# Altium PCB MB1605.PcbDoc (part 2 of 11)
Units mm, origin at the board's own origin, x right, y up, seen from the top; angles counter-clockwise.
Board outline 100 x 79.6 mm, 6 copper layers (Top Layer, Signal Layer 1, Signal Layer 2, Signal Layer 3, Signal Layer 4, Bottom Layer), stack 1.549 mm thick; 644 components, 529 nets, 2853 pads, 1462 vias.
Unrouted connection lines stored in the file: 2.
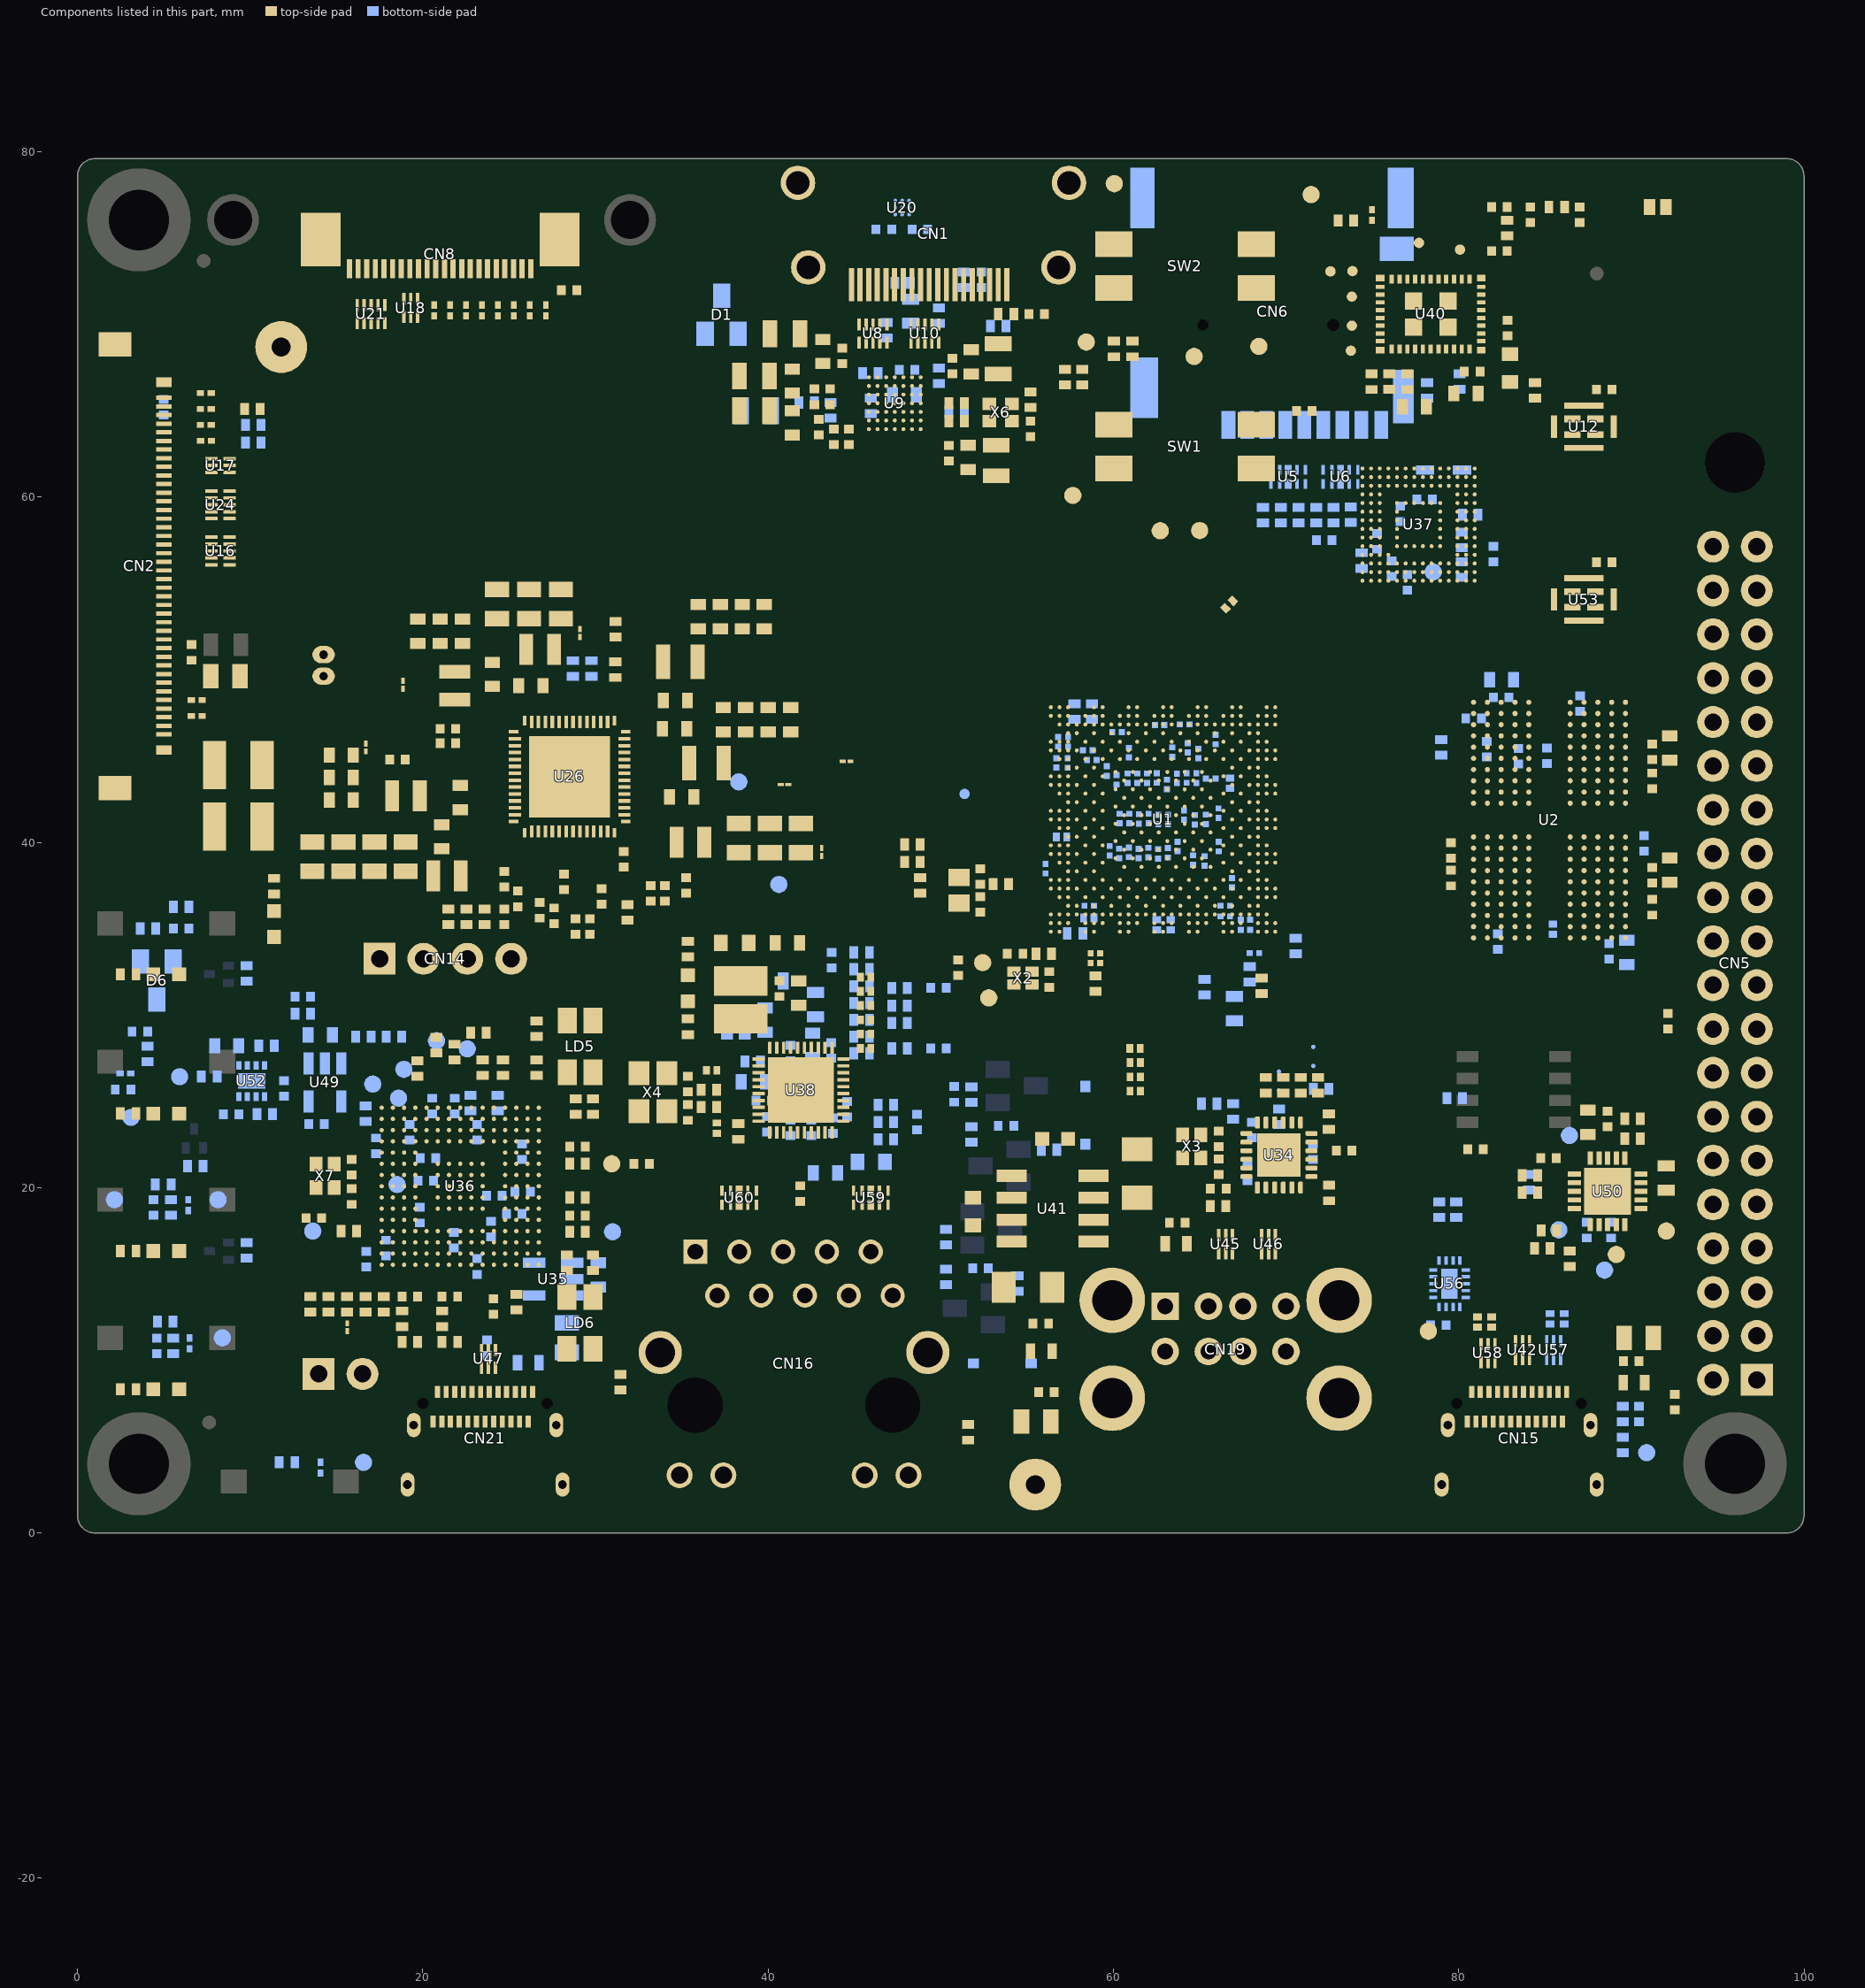
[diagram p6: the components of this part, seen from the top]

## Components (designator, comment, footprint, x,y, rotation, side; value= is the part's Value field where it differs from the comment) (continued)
R114 "" R0402 47.62,28.065 r0 bottom value=4K7
R120 "Resistor" R0201_H0P23 45.645,30.544 r180 top value=22R
R121 "Resistor" R0201_H0P23 45.645,29.72 r180 top value=22R
R122 "Resistor" R0402 58.2,66.95 r90 top value=1K
R123 "Resistor" R0402 61.1,68.575 r270 top value=1K
R124 "Resistor" R0402 60.025,68.575 r270 top value=1K
R125 "Resistor" R0402 26.59,29.207 r90 top value=10K
R126 "Resistor" R0402 4.963,20.187 r0 bottom value=330R
R127 "Resistor" R0402 5.082,12.237 r0 bottom value=330R
R128 "Resistor" R0402 5.413,18.85 r90 bottom value=100K
R129 "Resistor" R0402 20.79,28.257 r90 top value=0R
R130 "Resistor" R0402 28.85,24.7 r90 top value=330R
R131 "Resistor" R0402 29.858,24.7 r270 top value=1K
R132 "Resistor" R0402 29.85,15.644 r90 top value=330R
R133 "Resistor" R0402 28.35,15.644 r90 top value=1K
R134 "Resistor" R0402 21.84,27.857 r90 top value=33R
R135 "Resistor" R0402 5.532,10.837 r90 bottom value=100K
R136 "Resistor" R0402 2.936,8.327 r0 top value=360R
R137 "Resistor" R0402 6.813,21.252 r0 bottom value=100K
R138 "Resistor" R0402 2.936,24.294 r180 top value=270R
R139 "Resistor" R0402 4.056,27.75 r90 bottom value=1K
R140 "Resistor" R0402 7.627,26.441 r0 bottom value=100R
R141 "Resistor" R0402 9.786,16.377 r90 bottom value=100K
R142 "Resistor" R0402 2.936,16.327 r180 top value=300R
R143 "Resistor" R0402 9.786,32.411 r90 bottom value=100K
R144 "" R0402 2.936,32.361 r0 top value=120R
R147 "Resistor" R0201_H0P23 45.645,28.898 r180 top value=22R
R148 "Resistor" R0201_H0P23 45.644,28.065 r180 top value=22R
R149 "Resistor" R0201_H0P23 45.645,32.185 r180 top value=22R
R150 "Resistor" R0201_H0P23 45.645,31.365 r180 top value=22R
R151 "Resistor" R0402 35.35,33.82 r90 top value=270R
R153 "Resistor" R0402 23.465,26.957 r90 top value=33R
R154 "Resistor" R0402 24.64,26.957 r90 top value=0R
R155 "Resistor" R0402 26.59,26.957 r270 top value=0R
R156 "Resistor" R0402 19.69,26.907 r90 top value=10K
R158 "" R0402 35.35,29.32 r90 top value=4K7
R161 "Resistor" R0201_H0P23 62.506,35.225 r270 bottom value=22R
R162 "Resistor" R0402 51.775,23.075 r90 bottom value=100K
R164 "Resistor" R0201_H0P23 63.319,35.225 r270 bottom value=22R
R167 "Resistor" R0201_H0P23 61.245,28.065 r180 top value=22R
R173 "Resistor" R0201_H0P23 61.26,27.24 r180 top value=22R
R176 "Resistor" R0201_H0P23 36.725,26.8 r0 top value=22R
R178 "Resistor" R0201_H0P23 61.26,26.415 r180 top value=22R
R181 "Resistor" R0402 28.965,21.382 r0 top value=100R
R182 "" R0402 36.575,25.675 r0 top value=0R
R185 "Resistor" R0201_H0P23 61.26,25.59 r180 top value=22R
R187 "Resistor" R0402 50.297,14.825 r90 bottom value=100K
R188 "" R0402 36.575,24.675 r0 top value=0R
R191 "" R0402 46.82,24.8 r0 bottom value=1K5
R194 "Resistor" R0402 28.965,19.432 r0 top value=3K
R195 "" R0402 46.82,23.8 r0 bottom value=1K5
R196 "Resistor" R0201_H0P23 37.025,23.45 r90 top value=22R
R199 "" R0402 38.275,23.25 r270 top value=2K49
R200 "Resistor" R0402 54.438,14.437 r270 bottom value=100K
R205 "Resistor" R0402 46.82,22.8 r0 bottom value=10K
R207 "Resistor" R0402 15.715,17.482 r180 top value=33R
R209 "Resistor" R0402 28.965,17.443 r0 top value=33R
R210 "Resistor" R0402 11.386,37.465 r270 top value=270R
R211 "Resistor" R0402 25.415,13.362 r90 top value=0R
R212 "Resistor" R0402 13.49,13.232 r270 top value=0R
R213 "Resistor" R0402 14.54,13.232 r270 top value=10K
R214 "Resistor" R0402 15.615,13.232 r270 top value=10K
R215 "Resistor" R0402 16.69,13.232 r270 top value=10K
R216 "Resistor" R0402 17.74,13.232 r270 top value=5K1
R217 "Resistor" R0402 18.795,12.407 r270 top value=100K
R218 "Resistor" R0402 21.115,12.407 r270 top value=100K
R219 "Resistor" R0402 89.5,6.879 r90 bottom value=140K
R220 "Resistor" R0402 89.5,5.1 r90 bottom value=10K
R221 "Resistor" R0402 19.245,11.057 r0 top value=5K1
R222 "Resistor" R0402 21.565,11.057 r0 top value=5K1
R223 "Resistor" R0402 85.218,17.522 r180 top value=10K
R224 "Resistor" R0402 84.13,19.71 r180 top value=1K5
R225 "Resistor" R0603 92.025,20.56 r90 top value=22mR
R226 "Resistor" R0402 16.565,28.75 r0 bottom value=3K9
R227 "Resistor" R0402 18.315,28.75 r180 bottom value=100K
R228 "Resistor" R0402 84.13,20.71 r180 top value=1K5
R229 "Resistor" R0402 16.69,24.294 r90 bottom value=100K
R230 "Resistor" R0402 13.042,30.075 r0 bottom value=3K
R231 "Resistor" R0402 90.075,22.835 r0 top value=24K
R232 "Resistor" R0402 90.075,23.99 r180 top value=100K
R233 "" R0402 31.44,8.736 r90 top value=510R
R234 "" R0402 51.575,5.825 r270 top value=510R
R239 "Resistor" R0402 10.836,24.257 r180 bottom value=100K
R240 "Resistor" R0402 24.335,24.9 r270 bottom value=1K3
R241 "Resistor" R0402 22.765,24.9 r270 bottom value=1K8
R242 "Resistor" R0402 10.936,28.217 r0 bottom value=3K9
R245 "Resistor" R0402 48.355,39.873 r180 top value=1K5
R246 "Resistor" R0402 84.074,20.308 r270 bottom value=1K5
R248 "Resistor" R0402 80.657,58.98 r0 bottom value=10K
R250 "Resistor" R0402 57.744,47.57 r90 bottom value=200R
R251 "Resistor" R0402 58.751,47.57 r90 bottom value=200R
R260 "Resistor" R0402 28.689,50.071 r270 bottom value=1K5
R261 "Resistor" R0402 29.763,50.071 r270 bottom value=1K5
R267 "" R0402 57.773,34.723 r180 bottom value=0R
R269 "" R0402 58.956,31.808 r90 top value=0R
R272 "Resistor" R0402 48.805,37.505 r270 top value=10K
R286 "" R0402 67.89,32.365 r90 bottom value=0R
R292 "" R0402 45.42,29.72 r0 bottom value=4K7
R293 "" R0402 45.42,30.688 r0 bottom value=4K7
R303 "" R0402 45.42,27.785 r0 bottom value=4K7
R304 "" R0402 45.42,31.67 r0 bottom value=4K7
R305 "" R0402 45.42,32.651 r0 bottom value=4K7
R310 "" R0603 40.175,31.975 r0 bottom value=0R
R313 "" R0603 42.75,30.6 r90 bottom value=0R
R318 "" R0402 38.65,29.275 r90 bottom value=1K5
R319 "" R0402 37.625,29.275 r270 bottom value=4K7
R322 "" R0402 39.1,27.3 r180 bottom value=4K7
R323 "Resistor" R0402 72.483,19.687 r90 top value=10K
R324 "Resistor" R0402 72.477,23.817 r270 top value=10K
R325 "Resistor" R0402 79.775,25.178 r0 bottom value=1M
R327 "Resistor" R0402 86.438,15.875 r90 top value=100K
SB1 "SB_ON" SOLDER-BRIDGE_R0603-0R 69.587,26.223 r270 bottom
SB2 "SB_ON" SOLDER-BRIDGE_R0603-0R 71.577,27.65 r270 bottom
SW1 "SWITCH_2WAY" SWI_C&K_SDA02H1SBD_2POS 64.15,62.925 r90 top
SW2 "SWITCH_2WAY" SWI_C&K_SDA02H1SBD_2POS 64.15,73.375 r90 top
TP1 "Test Point" TP_SMD_0-6MM 80.075,74.331 r90 top
TP2 "Test Point" TP_SMD_1MM 2.136,19.3 r180 bottom
TP3 "Test Point" TP_SMD_1MM 8.136,19.3 r180 bottom
TP4 "Test Point" TP_SMD_1MM 40.618,37.56 r180 bottom
TP5 "Test Point" TP_SMD_1MM 8.386,11.3 r90 bottom
TP6 "Test Point" TP_SMD_1MM 3.095,24.07 r90 bottom
TP7 "Test Point" TP_SMD_1MM 5.913,26.425 r90 bottom
TP8 "Test_pin_conn_black" TP_PTH-1P02MM_TEST-TERMINAL_RS_101-2391_BLACK 11.799,68.689 r270 top value=TP
TP9 "Test Point" TP_SMD_0-6MM 77.7,74.725 r90 top
TP10 "Test Point" TP_SMD_0-6MM 73.754,68.475 r90 top
TP11 "Test Point" TP_SMD_1MM 86.412,23.025 r90 bottom
TP12 "Test Point" TP_SMD_1MM 52.427,33.031 r90 top
TP13 "Test Point" TP_SMD_1MM 20.79,28.507 r90 bottom
TP14 "Test Point" TP_SMD_0-6MM 73.81,69.925 r90 top
TP15 "Test Point" TP_SMD_1MM 64.995,58.058 r270 top
TP16 "Test Point" TP_SMD_1MM 62.711,58.047 r270 top
TP17 "Test Point" TP_SMD_0-6MM 72.573,73.072 r180 top
TP18 "Test Point" TP_SMD_0-6MM 51.376,42.803 r90 bottom
TP19 "Test Point" TP_SMD_0-6MM 73.844,73.087 r90 top
TP20 "Test Point" TP_SMD_0-6MM 73.81,71.607 r90 top
TP21 "Test Point" TP_SMD_1MM 78.516,55.665 r90 bottom
TP22 "Test Point" TP_SMD_1MM 16.565,4.09 r90 bottom
TP23 "Test Point" TP_SMD_1MM 57.651,60.096 r270 top
TP24 "Test Point" TP_SMD_1MM 64.675,68.143 r270 top
TP25 "Test Point" TP_SMD_1MM 68.425,68.725 r270 top
TP26 "Test Point" TP_SMD_1MM 18.9,26.85 r180 bottom
TP27 "Test Point" TP_SMD_1MM 18.505,20.182 r180 bottom
TP28 "Test Point" TP_SMD_1MM 17.098,26 r90 bottom
TP29 "Test Point" TP_SMD_1MM 18.59,25.182 r90 bottom
TP30 "Test Point" TP_SMD_1MM 38.304,43.502 r90 bottom
TP31 "Test Point" TP_SMD_1MM 58.425,68.975 r270 top
TP32 "Test Point" TP_SMD_1MM 71.45,77.525 r270 top
TP33 "Test Point" TP_SMD_1MM 30.94,21.382 r90 top
TP34 "Test Point" TP_SMD_1MM 78.243,11.686 r270 top
TP35 "Test Point" TP_SMD_1MM 90.888,4.65 r90 bottom
TP36 "Test Point" TP_SMD_1MM 85.798,17.551 r270 bottom
TP37 "Test Point" TP_SMD_1MM 88.449,15.218 r270 bottom
TP38 "Test Point" TP_SMD_1MM 89.125,16.131 r270 top
TP39 "Test Point" TP_SMD_1MM 92.025,17.49 r270 top
TP40 "Test Point" TP_SMD_1MM 30.985,17.443 r90 bottom
TP41 "Test Point" TP_SMD_1MM 13.625,17.482 r90 bottom
TP42 "Test Point" TP_SMD_1MM 52.78,30.993 r90 top
TP43 "Test Point" TP_SMD_1MM 22.575,28.041 r90 bottom
TP44 "Test Point" TP_SMD_1MM 60.05,78.15 r270 top
TP2000 "Test_pin_conn_black" TP_PTH-1P02MM_TEST-TERMINAL_RS_101-2391_BLACK 55.47,2.8 r90 top value=TP
U1 "STM32MP257FAK3" ICC_TFBGA424_14X14_P050_H1P20_CODE-B0A2 62.875,41.325 r0 top locked
U2 "MT53E1G32D2FW-046 WT:C" ICC_TFBGA200_10X14P5_P080_H1P05_PS0P3 85.26,41.29 r180 top locked
U3 "ESD-TRANSIL" ESD_ST0201 7.442,63.25 r0 top value=ESDZL5-1F4
U4 "ESD-TRANSIL" ESD_ST0201 7.429,66.025 r0 top value=ESDZL5-1F4
U5 "HSP051-4M10" ESD_UQFN-10L_2P5X1_P050 70.125,61.172 r0 bottom
U6 "HSP051-4M10" ESD_UQFN-10L_2P5X1_P050 73.154,61.172 r0 bottom
U7 "ESD-TRANSIL" ESD_ST0201 7.429,65.1 r0 top value=ESDZL5-1F4
U8 "ECMF4-40A100N10" ESD_UQFN-10L_2P25X1P4_P040 46.072,69.473 r180 top
U9 "ADV7535BCBZ" ICC_WLCSP49_3P46X3P46_P050 47.336,65.435 r0 top
U10 "ECMF4-40A100N10" ESD_UQFN-10L_2P25X1P4_P040 49.079,69.473 r180 top
U11 "ESD-TRANSIL" ESD_ST0201 20.65,70.813 r270 top value=ESDZL5-1F4
U12 "IMP34DT05TR" MIC_HCLGA_3X4X1_4LD 86.75,64.07 r90 top
U13 "ESD-TRANSIL" ESD_ST0201 7.429,64.175 r0 top value=ESDZL5-1F4
U14 "ESD-TRANSIL" ESD_ST0201 23.425,70.813 r270 top value=ESDZL5-1F4
U15 "ESD-TRANSIL" ESD_ST0201 14.062,3.778 r270 bottom value=ESDZL5-1F4
U16 "ECMF4-40A100N10" ESD_UQFN-10L_2P25X1P4_P040 8.277,56.875 r270 top
U17 "ECMF2-40A100N6" ESD_UQFN-6L_1P45X1P4_P040 8.277,61.825 r270 top
U18 "ECMF2-40A100N6" ESD_UQFN-6L_1P45X1P4_P040 19.3,70.95 r180 top
U19 "ESD-TRANSIL" ESD_ST0201 26.2,70.813 r270 top value=ESDZL5-1F4
U20 "HDMI05-CL02F3" ESD_FLIP-CHIP_BGA9_1P14X1P14_P040 47.764,76.769 r90 bottom
U21 "ECMF4-40A100N10" ESD_UQFN-10L_2P25X1P4_P040 17,70.6 r180 top
U22 "ESD-TRANSIL" ESD_ST0201 6.909,48.25 r0 top value=ESDZL5-1F4
U23 "ESD-TRANSIL" ESD_ST0201 6.909,47.325 r0 top value=ESDZL5-1F4
U24 "ECMF4-40A100N10" ESD_UQFN-10L_2P25X1P4_P040 8.277,59.55 r270 top
U25 "ESD-TRANSIL" ESD_ST0201 6.413,18.987 r270 bottom value=ESDZL5-1F4
U26 "STPMIC25APQR" ICC_QFN56-EPAD_6P5X6P5_P040 28.5,43.8 r90 top
U27 "ESD-TRANSIL" ESD_ST0201 6.493,10.975 r270 bottom value=ESDZL5-1F4
U28 "ESD-TRANSIL" ESD_ST0201 2.77,26.627 r180 bottom value=ESDALC6V1-1U2
U29 "ESD-TRANSIL" ESD_ST0201 21.575,70.813 r270 top value=ESDZL5-1F4
U31 "ESD-TRANSIL" ESD_ST0201 22.5,70.813 r270 top value=ESDZL5-1F4
U32 "ESD-TRANSIL" ESD_ST0201 24.35,70.813 r270 top value=ESDZL5-1F4
U33 "ESD-TRANSIL" ESD_ST0201 25.275,70.813 r270 top value=ESDZL5-1F4
U34 "USB2422-I/MJ" ICC_SQFN24-EPAD_4X4_P050 69.587,21.888 r90 top
U35 "ST730M33R" ICC_SOT23-5L_H1P45 27.546,14.7 r270 bottom
U36 "STLINK-V3EC" ICC_UFBGA201_176+25_10X10_P065 22.165,20.082 r0 top value=STM32F723IEK6
U37 "eMMC_THGBMUG6C1LBAIL" ICC_WFBGA153_13X11P5_P050 77.675,58.405 r0 top value=THGBMUG6C1LBAIL
U38 "RTL8211F-CG" ICC_QFN40-EPAD_5X5_P040 41.9,25.65 r90 top
U39 "ESD-TRANSIL" ESD_ST0201 27.125,70.813 r270 top value=ESDZL5-1F4
U40 "LBEE5KL1YN-814" MOD_WLAN-BT_MURATA_LBEE5KL1YN-814 78.375,70.6 r180 top
U41 "STMPS2252MTR" ICC_SO8_5X4_P127 56.479,18.778 r270 top
U42 "ECMF2-40A100N6" ESD_UQFN-6L_1P45X1P4_P040 83.7,10.598 r0 top
U43 "ESD-TRANSIL" ESD_QFN1610_2N_1K_2A 90.15,8.702 r0 top value=ESDA25P35-1U1M
U44 "ESD-TRANSIL" ESD_QFN1610_2N_1K_2A 63.625,16.76 r0 top value=ESDA7P120-1U1M
U45 "ECMF2-40A100N6" ESD_UQFN-6L_1P45X1P4_P040 66.5,16.725 r0 top
U46 "ECMF2-40A100N6" ESD_UQFN-6L_1P45X1P4_P040 68.984,16.725 r0 top
U47 "ECMF2-40A100N6" ESD_UQFN-6L_1P45X1P4_P040 23.8,10.086 r0 top
U48 "ESD-TRANSIL" ESD_QFN1610_2N_1K_2A 26.11,9.865 r0 bottom value=ESDA25P35-1U1M
U49 "STMPS2151STR" MOS_SOT23-5L 14.331,26.093 r0 bottom
U50 "TCPP03-M20" ICC_QFN20-EPAD_4X4_P050 88.625,19.785 r90 top
U51 "ESD-TRANSIL" ESD_QFN1610_2N_1K_2A 55.82,10.535 r180 top value=ESDA7P120-1U1M
U52 "TPS259535DSG" ICC_WSON8-EPAD_2X2_P050 10.086,26.177 r90 bottom
U53 "IMP34DT05TR" MIC_HCLGA_3X4X1_4LD 86.75,54.07 r90 top
U54 "ESD-TRANSIL" ESD_ST0201 74.975,76.338 r90 top value=ESDZL5-1F4
U56 "FUSB340TMX" ICC_UQFN18-EPAD_2X2P80_P040 79.468,14.436 r0 bottom
U57 "ECMF2-40A100N6" ESD_UQFN-6L_1P45X1P4_P040 85.498,10.598 r180 bottom
U58 "ECMF2-40A100N6" ESD_UQFN-6L_1P45X1P4_P040 81.7,10.413 r0 top
U59 "HSP051-4M10" ESD_UQFN-10L_2P5X1_P050 45.945,19.422 r180 top
U60 "HSP051-4M10" ESD_UQFN-10L_2P5X1_P050 38.325,19.422 r180 top
X1 "XTAL_2_PINS" CRY_NX2012SA_2P 51.059,37.225 r270 top value=32.768KHz
X2 "XTAL_4_PINS" CRY_NX1612SA_4P 54.759,32.135 r180 top value=40MHz
X3 "XTAL_4_PINS" CRY_NX2016SA_4P 64.543,22.39 r90 top value=24MHz
X4 "XTAL_4_PINS" CRY_NX3225HA_4P 33.325,25.525 r270 top value=25MHz
X6 "OSCILLATOR_4_PINS" CRY_NZ2016SH_4P 53.463,64.895 r180 top value=24MHz
X7 "XTAL_4_PINS" CRY_NX2016SA_4P 14.34,20.682 r270 top value=24MHz

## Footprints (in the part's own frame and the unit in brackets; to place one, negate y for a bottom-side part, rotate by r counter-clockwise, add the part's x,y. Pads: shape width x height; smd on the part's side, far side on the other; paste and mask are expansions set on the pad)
C0201_H0P3 [mm] "MCD-00699"
  rect 0.4x0.5 smd mask+0.05: 1(-0.3,0) 2(0.3,0)
  body extent -0.32,-0.17 0.32,0.17, height 0.33
C0201_H0P5 [mm] "MCD-01534"
  rect 0.4x0.5 smd mask+0.05: 1(-0.3,0) 2(0.3,0)
  body extent -0.35,-0.2 0.35,0.2, height 0.55
C0201_MURATA_GRM033_H0P3 [mm] "GRM033R60J105ME11"
  rect 0.35x0.35 smd mask+0.05: 1(-0.275,0) 2(0.275,0)
  body extent -0.32,-0.17 0.32,0.17, height 0.33
C0402 [mm]
  rect 0.51x0.56 smd mask+0.05: 1(-0.45,0) 2(0.45,0)
  body extent -0.5,-0.3 0.5,0.3, height 0.4
C0603 [mm]
  rect 0.64x0.89 smd mask+0.05: 1(-0.7,0) 2(0.7,0)
  silkscreen extent -1.05,-0.55 1.02,0.55, body extent -0.9,-0.5 0.9,0.5, height 1.4
C0805 [mm]
  rect 0.9x1.4 smd mask+0.05: 1(-0.85,0) 2(0.85,0)
  silkscreen extent -1.3,-0.77 1.3,0.77, body extent -1.1,-0.7 1.1,0.7, height 1.35
C1206_H1P6 [mm]
  rect 1.4x1.78 smd mask+0.05: 1(-1.4,0) 2(1.4,0)
  silkscreen extent -2.12,-0.97 2.15,0.97, body extent -1.7,-0.9 1.7,0.9, height 1.8
CON_DUAL-USB-TYPE-A_CONEXCON_5600-3081 [mm]
  round 1.6 hole 0.92: B1(-3.5,13.01) B2(-1,13.01) B3(1,13.01) B4(3.5,13.01) T2(-1,15.63) T3(1,15.63) T4(3.5,15.63)
  round 3.8 hole 2.33: CH1(6.57,10.3) CH2(-6.57,10.3) CH3(-6.57,15.98) CH4(6.57,15.98)
  rect 1.6x1.6 hole 0.92: T1(-3.5,15.63)
  silkscreen extent -7.3,-0.4 7.3,17.85, body extent -7.83,-0.6 7.87,17.85, height 16.2
CON_HDMI_FCI-AMPHENOL_10029449-001RLF [mm]
  rect 0.3x1.9 smd mask+0.05: 1(4.75,8.5) 2(4.25,8.5) 3(3.75,8.5) 4(3.25,8.5) 5(2.75,8.5) 6(2.25,8.5) 7(1.75,8.5) 8(1.25,8.5) 9(0.75,8.5) 10(0.25,8.5) 11(-0.25,8.5) 12(-0.75,8.5) 13(-1.25,8.5) 14(-1.75,8.5) 15(-2.25,8.5) 16(-2.75,8.5) 17(-3.25,8.5) 18(-3.75,8.5) 19(-4.25,8.5)
  round 2 hole 1.35 mask+0.1: 20(7.25,7.5) 21(-7.25,7.5) 22(7.85,2.6) 23(-7.85,2.6)
  silkscreen extent -7.5,-1 7.5,8, body extent -8.1,-1 8.1,8.9, height 6.3
CON_I-PEX_20455-040E-76 [mm] "MCD-03562"
  rect 0.25x0.9 smd mask+0.05: 1(-9.75,0.5) 2(-9.25,0.5) 3(-8.75,0.5) 4(-8.25,0.5) 5(-7.75,0.5) 6(-7.25,0.5) 7(-6.75,0.5) 8(-6.25,0.5) 9(-5.75,0.5) 10(-5.25,0.5) 11(-4.75,0.5) 12(-4.25,0.5) 13(-3.75,0.5) 14(-3.25,0.5) 15(-2.75,0.5) 16(-2.25,0.5) 17(-1.75,0.5) 18(-1.25,0.5) 19(-0.75,0.5) 20(-0.25,0.5) 21(0.25,0.5) 22(0.75,0.5) 23(1.25,0.5) 24(1.75,0.5) 25(2.25,0.5) 26(2.75,0.5) 27(3.25,0.5) 28(3.75,0.5) 29(4.25,0.5) 30(4.75,0.5) 31(5.25,0.5) 32(5.75,0.5) 33(6.25,0.5) 34(6.75,0.5) 35(7.25,0.5) 36(7.75,0.5) 37(8.25,0.5) 38(8.75,0.5) 39(9.25,0.5) 40(9.75,0.5)
  rect 1.4x1.9 smd mask+0.05: 41(-12.85,-2.32) 44(12.85,-2.32)
  rect 0.55x0.9 smd mask+0.05: 42(-10.65,0.5) 43(10.65,0.5)
  silkscreen extent -13.13,-2.78 13.13,0.92, body extent -13.13,-3.05 13.12,0.9, height 1.03
CON_MICROSD_YAMAICHI_PJS008-2003-1 [mm] "WITH POSITIONNING PINS"
  rect 1.6x0.8 smd paste+0 mask+0.05: 1(-15.6,-2.525) 2(-15.6,-1.425) 3(-15.6,-0.325) 4(-15.6,0.775) 5(-15.6,1.875) 6(-15.6,2.975) 7(-15.6,4.075) 8(-15.6,5.175) 9(-15.6,6.325)
  rect 1.4x1.95 smd paste+0 mask+0.05: 10(-5.4,7.225)
  rect 3.5x1.5 smd paste+0 mask+0.05: 11(-2.45,7.45)
  rect 3.5x1.4 smd paste+0 mask+0.05: 12(-2.45,-7.5)
  rect 3.5x1.6 smd paste+0 mask+0.05: 13(-13.45,-7.4)
  rect 3.1x1.2 smd paste+0 mask+0.05: 14(-13.95,7.6)
  round 0 hole 0.65 unplated mask+0.05: NPTH1(-9.8,-4)
  round 0 hole 0.7 unplated mask+0.05: NPTH2(-9.8,3.55)
  silkscreen extent -15.32,-7.25 5.65,7.25, body extent -15.25,-7.25 -0.45,7.42, height 2
CON_MOLEX_53047-0210 [mm]
  oval 1x1.3 hole 0.5 mask+0.05: 1(-0.625,0) 2(0.625,0)
  silkscreen extent -2.12,-1.15 2.13,2.05, body extent -2.13,-1.15 2.13,2.05, height 4.2
CON_RJ45_YD_48F-01GYDXNL_LED-P [mm]
  rect 1.4x1.4 hole 0.9 mask+0.05: 1(-5.715,16.29)
  round 1.4 hole 0.9 mask+0.05: 2(-4.445,13.75) 3(-3.175,16.29) 4(-1.905,13.75) 5(-0.635,16.29) 6(0.635,13.75) 7(1.905,16.29) 8(3.175,13.75) 9(4.445,16.29) 10(5.715,13.75)
  round 1.5 hole 1 mask+0.05: 11(-6.63,3.34) 12(-4.09,3.34) 13(4.09,3.34) 14(6.63,3.34)
  round 2.5 hole 1.7 mask+0.05: 15(7.75,10.45) 16(-7.75,10.45)
  round 1 hole 3.2 unplated mask+0.1: 17(-5.715,7.4) 18(5.715,7.4)
  Multi-Layer keep-out circle w0.01: c5.715,7.4 r1.9
  Multi-Layer keep-out circle w0.01: c-5.715,7.4 r1.9
  silkscreen extent -10.54,-3.5 11.26,18.34, body extent -11.4,-3.5 11.39,18.34, height 17
CON_SAMTEC_TSW-102-07-G-S [mm]
  rect 1.85x1.85 / inner round 1.85 / far side rect 1.85x1.85 hole 1 mask+0.05: 1(-1.27,0)
  round 1.85 hole 1 mask+0.05: 2(1.27,0)
  silkscreen extent -2.58,-1.3 2.58,1.3, body extent -2.67,-1.3 2.58,1.3, height 8.38
CON_SAMTEC_TSW-104-07-G-S [mm]
  rect 1.85x1.85 / inner round 1.85 / far side rect 1.85x1.85 hole 1 mask+0.05: 1(-3.81,0)
  round 1.85 hole 1 mask+0.05: 2(-1.27,0) 3(1.27,0) 4(3.81,0)
  silkscreen extent -5.12,-1.3 5.12,1.3, body extent -5.21,-1.37 5.18,1.37, height 8.38
CON_SAMTEC_TSW-120-07-G-D [mm]
  rect 1.85x1.85 / inner round 1.85 / far side rect 1.85x1.85 hole 1 mask+0.05: 1(-24.13,-1.27)
  round 1.85 hole 1 mask+0.05: 2(-24.13,1.27) 3(-21.59,-1.27) 4(-21.59,1.27) 5(-19.05,-1.27) 6(-19.05,1.27) 7(-16.51,-1.27) 8(-16.51,1.27) 9(-13.97,-1.27) 10(-13.97,1.27) 11(-11.43,-1.27) 12(-11.43,1.27) 13(-8.89,-1.27) 14(-8.89,1.27) 15(-6.35,-1.27) 16(-6.35,1.27) 17(-3.81,-1.27) 18(-3.81,1.27) 19(-1.27,-1.27) 20(-1.27,1.27) 21(1.27,-1.27) 22(1.27,1.27) 23(3.81,-1.27) 24(3.81,1.27) 25(6.35,-1.27) 26(6.35,1.27) 27(8.89,-1.27) 28(8.89,1.27) 29(11.43,-1.27) 30(11.43,1.27) 31(13.97,-1.27) 32(13.97,1.27) 33(16.51,-1.27) 34(16.51,1.27) 35(19.05,-1.27) 36(19.05,1.27) 37(21.59,-1.27) 38(21.59,1.27) 39(24.13,-1.27) 40(24.13,1.27)
  silkscreen extent -25.4,-2.54 25.4,2.54, body extent -25.4,-2.55 25.4,2.54, height 8.38
CON_TE-CONNECTIVITY_2-1734592-2_INV [mm] "MCD-03600"
  rect 0.3x1.1 smd mask+0.05: 1(5.25,1.7) 2(4.75,1.7) 3(4.25,1.7) 4(3.75,1.7) 5(3.25,1.7) 6(2.75,1.7) 7(2.25,1.7) 8(1.75,1.7) 9(1.25,1.7) 10(0.75,1.7) 11(0.25,1.7) 12(-0.25,1.7) 13(-0.75,1.7) 14(-1.25,1.7) 15(-1.75,1.7) 16(-2.25,1.7) 17(-2.75,1.7) 18(-3.25,1.7) 19(-3.75,1.7) 20(-4.25,1.7) 21(-4.75,1.7) 22(-5.25,1.7)
  rect 2.3x3.1 smd mask+0.05: S1(6.92,0) S2(-6.92,0)
  silkscreen extent -8.22,-3.06 8.21,1.35, body extent -8.22,-3.06 8.21,2.05, height 2.05
CON_USB-TYPEC_AMPHENOL_12401826E412A [mm] "MCD-03232"
  round 0 hole 0.65 unplated mask+0.05: 0(-3.6,0)
  round 0 hole 0.65 slot 0.95 at 0 deg unplated mask+0.05: 0(3.6,0)
  rect 0.3x0.7 smd mask+0.05: A1(-2.75,0.66) A2(-2.25,0.66) A3(-1.75,0.66) A4(-1.25,0.66) A5(-0.75,0.66) A6(-0.25,0.66) A7(0.25,0.66) A8(0.75,0.66) A9(1.25,0.66) A10(1.75,0.66) A11(2.25,0.66) A12(2.75,0.66) B1(2.5,-1.04) B2(2,-1.04) B3(1.5,-1.04) B4(1,-1.04) B5(0.5,-1.04) B6(0,-1.04) B7(-0.5,-1.04) B8(-1,-1.04) B9(-1.5,-1.04) B10(-2,-1.04) B11(-2.5,-1.04) B12(-3,-1.04)
  oval 0.8x1.4 hole 0.5 slot 1.1 at 90 deg mask+0.05: SH1(-4.13,-1.25) SH2(4.13,-1.25) SH3(-4.49,-4.7) SH4(4.49,-4.7)
  Top Layer keep-out region: -3.725,-7.215 3.775,-7.215 3.775,-1.925 -3.725,-1.925
  silkscreen extent -4.6,-9.59 4.6,0.91, body extent -4.6,-9.59 4.6,0.91, height 3.25
CPOL_TCJ-B_1210_H210 [mm] "MCD-01791"
  rect 1.35x2.8 smd mask+0.05: 1(-1.375,0) 2(1.375,0)
  silkscreen extent -2.33,-1.68 1.85,1.68, body extent -1.85,-1.5 1.85,1.5, height 2.11
CRY_NX1612SA_4P [mm] "MCD-02262"
  rect 0.75x0.6 smd mask+0.038: 1(-0.525,-0.375) 2(0.525,-0.375) 3(0.525,0.375) 4(-0.525,0.375)
  silkscreen extent -1.02,-0.8 0.03,0.6, body extent -0.8,-0.6 0.8,0.6, height 0.51
CRY_NX2012SA_2P [mm]
  rect 1x1.25 smd mask+0.05: 1(-0.75,0) 2(0.75,0)
  silkscreen extent -1.05,-0.75 1.05,0.75, body extent -1.05,-0.63 1.05,0.63, height 0.6
CRY_NX2016SA_4P [mm]
  rect 0.85x0.75 smd mask+0.05: 1(-0.675,-0.525) 2(0.675,-0.525) 3(0.675,0.525) 4(-0.675,0.525)
  silkscreen extent -1.22,-1.02 1.05,0.85, body extent -1.05,-0.85 1.05,0.85, height 0.7
CRY_NX3225HA_4P [mm]
  rect 1.4x1.2 smd mask+0.05: 1(-1.1,-0.8) 2(1.1,-0.8) 3(1.1,0.8) 4(-1.1,0.8)
  silkscreen extent -1.9,-1.5 1.65,1.3, body extent -1.66,-1.31 1.66,1.31, height 0.91
CRY_NZ2016SH_4P [mm] "MCD-01627"
  rect 0.8x0.7 smd mask+0.05: 1(-0.65,-0.5) 2(0.65,-0.5) 3(0.65,0.5) 4(-0.65,0.5)
  silkscreen extent -1.17,-0.97 1.05,0.85, body extent -1.05,-0.85 1.05,0.85, height 0.71
DIO_SOD123_1A_2K_H1P45 [mm] "MCD-03688"
  rect 0.65x0.57 smd mask+0.05: 1(1.675,0) 2(-1.675,0)
  silkscreen extent -1.95,-0.9 1.45,0.9, body extent -1.95,-0.9 1.95,0.9, height 1.18
DIO_SOD323 [mm]
  rect 1.06x0.54 smd mask+0.05: 1(-1.07,0) 2(1.07,0)
  silkscreen extent -0.9,-0.72 0.9,0.72, body extent -1.3,-0.78 1.3,0.78, height 1.17
DIO_SOT23 [mm]
  rect 1x1.4 smd mask+0.05: 1(-0.95,-1.1) 2(0.95,-1.1) 3(0,1.1)
  silkscreen extent -1.63,-0.82 1.63,0.82, body extent -1.56,-1.25 1.56,1.25, height 1.1
DIO_SOT23_SC59_1A_2NC_3K_H1P4 [mm] "MCD-01524"
  rect 1x1.4 smd mask+0.05: 1(-0.95,-1.1) 2(0.95,-1.1) 3(0,1.1)
  silkscreen extent -1.58,-0.87 1.58,0.87, body extent -1.55,-1.4 1.55,1.4, height 1.4
ESD_FLIP-CHIP_BGA9_1P14X1P14_P040 [mm] "MCD-02316"
  round 0.22 smd paste+0.02 mask+0.04: A1(-0.4,0.4) A2(0,0.4) A3(0.4,0.4) B1(-0.4,0) B2(0,0) B3(0.4,0) C1(-0.4,-0.4) C2(0,-0.4) C3(0.4,-0.4)
  silkscreen extent -0.72,-0.61 0.61,0.72, body extent -0.59,-0.59 0.59,0.59, height 0.67
ESD_QFN1610_2N_1K_2A [mm] "DFN, 2-Leads, Body 1.60x1.00mm"
  rect 0.55x0.9 smd mask+0.05: 1(-0.625,0) 2(0.625,0)
  silkscreen extent -1.02,-0.58 0.85,0.58, body extent -0.85,-0.55 0.85,0.55, height 0.6
ESD_ST0201 [mm]
  rect 0.425x0.33 smd mask+0.05: 1(-0.312,0) 2(0.312,0)
  silkscreen extent -0.55,-0.3 0.33,0.3, body extent -0.34,-0.18 0.34,0.18, height 0.34
ESD_UQFN-6L_1P45X1P4_P040 [mm] "MCD-03060"
  rect 0.2x0.7 smd mask+0.05: 1(-0.4,-0.525) 2(0,-0.525) 3(0.4,-0.525) 4(0.4,0.525) 5(0,0.525) 6(-0.4,0.525)
  body extent -0.72,-0.7 0.72,0.7, height 0.51
ESD_UQFN-10L_2P5X1_P050 [mm]
  rect 0.2x0.58 smd mask+0.05: 1(-1,-0.41) 2(-0.5,-0.41) 4(0.5,-0.41) 5(1,-0.41) 6(1,0.41) 7(0.5,0.41) 9(-0.5,0.41) 10(-1,0.41)
  rect 0.4x0.58 smd mask+0.05: 3(0,-0.41) 8(0,0.41)
  silkscreen extent -1.38,-0.63 1.38,0.63, body extent -1.3,-0.55 1.3,0.55, height 0.51
ESD_UQFN-10L_2P25X1P4_P040 [mm] "MCD-03059"
  rect 0.2x0.7 smd mask+0.05: 1(-0.8,-0.525) 2(-0.4,-0.525) 3(0,-0.525) 4(0.4,-0.525) 5(0.8,-0.525) 6(0.8,0.525) 7(0.4,0.525) 8(0,0.525) 9(-0.4,0.525) 10(-0.8,0.525)
  body extent -1.12,-0.7 1.12,0.7, height 0.51
FIL_0603_H0P65 [mm]
  rect 0.8x0.95 smd mask+0.05: 1(-0.8,0) 2(0.8,0)
  silkscreen extent -1.33,-0.6 1.33,0.6, body extent -0.87,-0.47 0.87,0.47, height 0.65
ICC_QFN20-EPAD_4X4_P050 [mm] "MCD-02130"
  rect 0.75x0.3 smd mask+0.05: 1(-1.925,1) 2(-1.925,0.5) 3(-1.925,0) 4(-1.925,-0.5) 5(-1.925,-1) 11(1.925,-1) 12(1.925,-0.5) 13(1.925,0) 14(1.925,0.5) 15(1.925,1)
  rect 0.3x0.75 smd mask+0.05: 6(-1,-1.925) 7(-0.5,-1.925) 8(0,-1.925) 9(0.5,-1.925) 10(1,-1.925) 16(1,1.925) 17(0.5,1.925) 18(0,1.925) 19(-0.5,1.925) 20(-1,1.925)
  rect 2.7x2.7 smd mask+0.05: 21(0,0)
  silkscreen extent -2.07,-2.07 2.07,2.07, body extent -2.13,-2.13 2.13,2.13, height 1.01
ICC_QFN40-EPAD_5X5_P040 [mm]
  rect 0.7x0.2 smd mask+0.05: 1(-2.45,1.8) 2(-2.45,1.4) 3(-2.45,1) 4(-2.45,0.6) 5(-2.45,0.2) 6(-2.45,-0.2) 7(-2.45,-0.6) 8(-2.45,-1) 9(-2.45,-1.4) 10(-2.45,-1.8) 21(2.45,-1.8) 22(2.45,-1.4) 23(2.45,-1) 24(2.45,-0.6) 25(2.45,-0.2) 26(2.45,0.2) 27(2.45,0.6) 28(2.45,1) 29(2.45,1.4) 30(2.45,1.8)
  rect 0.2x0.7 smd mask+0.05: 11(-1.8,-2.45) 12(-1.4,-2.45) 13(-1,-2.45) 14(-0.6,-2.45) 15(-0.2,-2.45) 16(0.2,-2.45) 17(0.6,-2.45) 18(1,-2.45) 19(1.4,-2.45) 20(1.8,-2.45) 31(1.8,2.45) 32(1.4,2.45) 33(1,2.45) 34(0.6,2.45) 35(0.2,2.45) 36(-0.2,2.45) 37(-0.6,2.45) 38(-1,2.45) 39(-1.4,2.45) 40(-1.8,2.45)
  rect 3.8x3.8 smd mask+0.05: 41(0,0)
  silkscreen extent -2.5,-2.5 2.5,2.5, body extent -2.5,-2.5 2.5,2.5, height 0.91
ICC_QFN56-EPAD_6P5X6P5_P040 [mm] "MCD-03000"
  rect 0.55x0.21 smd mask+0.05: 1(-3.245,2.6) 14(-3.245,-2.6) 29(3.245,-2.6) 42(3.245,2.6)
  rect 0.7x0.21 smd mask+0.05: 2(-3.17,2.2) 3(-3.17,1.8) 4(-3.17,1.4) 5(-3.17,1) 6(-3.17,0.6) 7(-3.17,0.2) 8(-3.17,-0.2) 9(-3.17,-0.6) 10(-3.17,-1) 11(-3.17,-1.4) 12(-3.17,-1.8) 13(-3.17,-2.2) 30(3.17,-2.2) 31(3.17,-1.8) 32(3.17,-1.4) 33(3.17,-1) 34(3.17,-0.6) 35(3.17,-0.2) 36(3.17,0.2) 37(3.17,0.6) 38(3.17,1) 39(3.17,1.4) 40(3.17,1.8) 41(3.17,2.2)
  rect 0.21x0.55 smd mask+0.05: 15(-2.6,-3.245) 28(2.6,-3.245) 43(2.6,3.245) 56(-2.6,3.245)
  rect 0.21x0.7 smd mask+0.05: 16(-2.2,-3.17) 17(-1.8,-3.17) 18(-1.4,-3.17) 19(-1,-3.17) 20(-0.6,-3.17) 21(-0.2,-3.17) 22(0.2,-3.17) 23(0.6,-3.17) 24(1,-3.17) 25(1.4,-3.17) 26(1.8,-3.17) 27(2.2,-3.17) 44(2.2,3.17) 45(1.8,3.17) 46(1.4,3.17) 47(1,3.17) 48(0.6,3.17) 49(0.2,3.17) 50(-0.2,3.17) 51(-0.6,3.17) 52(-1,3.17) 53(-1.4,3.17) 54(-1.8,3.17) 55(-2.2,3.17)
  rect 4.7x4.7 smd mask+0.05: 57(0,0)
  Top Layer region: -2.495,-2.97 -2.495,-2.82 -2.555,-2.82 -2.705,-2.97
  Top Layer region: 2.495,2.97 2.495,2.82 2.555,2.82 2.705,2.97
  Top Layer region: 2.97,2.495 2.82,2.495 2.82,2.555 2.97,2.705
  Top Layer region: 2.495,-2.97 2.495,-2.82 2.555,-2.82 2.705,-2.97
  Top Layer region: 2.97,-2.495 2.82,-2.495 2.82,-2.555 2.97,-2.705
  Top Layer region: -2.495,2.97 -2.495,2.82 -2.555,2.82 -2.705,2.97
  Top Layer region: -2.97,-2.495 -2.82,-2.495 -2.82,-2.555 -2.97,-2.705
  Top Layer region: -2.97,2.495 -2.82,2.495 -2.82,2.555 -2.97,2.705
  silkscreen extent -3.44,3 -3.01,3.42, body extent -3.25,-3.25 3.25,3.25, height 0.91
ICC_SO8_5X4_P127 [mm]
  rect 0.7x1.75 smd mask+0.05: 1(-1.905,-2.375) 2(-0.635,-2.375) 3(0.635,-2.375) 4(1.905,-2.375) 5(1.905,2.375) 6(0.635,2.375) 7(-0.635,2.375) 8(-1.905,2.375)
  silkscreen extent -2.73,-3.25 2.58,2, body extent -2.57,-3 2.57,3, height 1.75
ICC_SOT23-5L_H1P45 [mm]
  rect 0.6x1.3 smd mask+0.05: 1(-0.95,-1.1) 2(0,-1.1) 3(0.95,-1.1) 4(0.95,1.1) 5(-0.95,1.1)
  silkscreen extent -1.75,-1.68 1.6,0.97, body extent -1.52,-1.25 1.52,1.25, height 1.45
ICC_SQFN24-EPAD_4X4_P050 [mm] "MCD-02348"
  rrect50% 0.69x0.28 smd mask+0.05: 1(-1.883,1.25) 2(-1.883,0.75) 3(-1.883,0.25) 4(-1.883,-0.25) 5(-1.883,-0.75) 6(-1.883,-1.25) 13(1.883,-1.25) 14(1.883,-0.75) 15(1.883,-0.25) 16(1.883,0.25) 17(1.883,0.75) 18(1.883,1.25)
  rrect50% 0.28x0.69 smd mask+0.05: 7(-1.25,-1.883) 8(-0.75,-1.883) 9(-0.25,-1.883) 10(0.25,-1.883) 11(0.75,-1.883) 12(1.25,-1.883) 19(1.25,1.883) 20(0.75,1.883) 21(0.25,1.883) 22(-0.25,1.883) 23(-0.75,1.883) 24(-1.25,1.883)
  rect 2.5x2.5 smd paste-10 mask+0.05: 25(0,0)
  silkscreen extent -2.22,-2 2,2.22, body extent -2.05,-2.05 2.05,2.05, height 1.1
ICC_TFBGA200_10X14P5_P080_H1P05_PS0P3 [mm] "MCD-04012"
  round 0.3 smd mask+0.05: A1(-4.4,6.825) A2(-3.6,6.825) A3(-2.8,6.825) A4(-2,6.825) A5(-1.2,6.825) A8(1.2,6.825) A9(2,6.825) A10(2.8,6.825) A11(3.6,6.825) A12(4.4,6.825) AA1(-4.4,-6.175) AA2(-3.6,-6.175) AA3(-2.8,-6.175) AA4(-2,-6.175) AA5(-1.2,-6.175) AA8(1.2,-6.175) AA9(2,-6.175) AA10(2.8,-6.175) AA11(3.6,-6.175) AA12(4.4,-6.175) AB1(-4.4,-6.825) AB2(-3.6,-6.825) AB3(-2.8,-6.825) AB4(-2,-6.825) AB5(-1.2,-6.825) AB8(1.2,-6.825) AB9(2,-6.825) AB10(2.8,-6.825) AB11(3.6,-6.825) AB12(4.4,-6.825) B1(-4.4,6.175) B2(-3.6,6.175) B3(-2.8,6.175) B4(-2,6.175) B5(-1.2,6.175) B8(1.2,6.175) B9(2,6.175) B10(2.8,6.175) B11(3.6,6.175) B12(4.4,6.175) C1(-4.4,5.525) C2(-3.6,5.525) C3(-2.8,5.525) C4(-2,5.525) C5(-1.2,5.525) C8(1.2,5.525) C9(2,5.525) C10(2.8,5.525) C11(3.6,5.525) C12(4.4,5.525) D1(-4.4,4.875) D2(-3.6,4.875) D3(-2.8,4.875) D4(-2,4.875) D5(-1.2,4.875) D8(1.2,4.875) D9(2,4.875) D10(2.8,4.875) D11(3.6,4.875) D12(4.4,4.875) E1(-4.4,4.225) E2(-3.6,4.225) E3(-2.8,4.225) E4(-2,4.225) E5(-1.2,4.225) E8(1.2,4.225) E9(2,4.225) E10(2.8,4.225) E11(3.6,4.225) E12(4.4,4.225) F1(-4.4,3.575) F2(-3.6,3.575) F3(-2.8,3.575) F4(-2,3.575) F5(-1.2,3.575) F8(1.2,3.575) F9(2,3.575) F10(2.8,3.575) F11(3.6,3.575) F12(4.4,3.575) G1(-4.4,2.925) G2(-3.6,2.925) G3(-2.8,2.925) G4(-2,2.925) G5(-1.2,2.925) G8(1.2,2.925) G9(2,2.925) G10(2.8,2.925) G11(3.6,2.925) G12(4.4,2.925) H1(-4.4,2.275) H2(-3.6,2.275) H3(-2.8,2.275) H4(-2,2.275) H5(-1.2,2.275) H8(1.2,2.275) H9(2,2.275) H10(2.8,2.275) H11(3.6,2.275) H12(4.4,2.275) J1(-4.4,1.625) J2(-3.6,1.625) J3(-2.8,1.625) J4(-2,1.625) J5(-1.2,1.625) J8(1.2,1.625) J9(2,1.625) J10(2.8,1.625) J11(3.6,1.625) J12(4.4,1.625) K1(-4.4,0.975) K2(-3.6,0.975) K3(-2.8,0.975) K4(-2,0.975) K5(-1.2,0.975) K8(1.2,0.975) K9(2,0.975) K10(2.8,0.975) K11(3.6,0.975) K12(4.4,0.975) N1(-4.4,-0.975) N2(-3.6,-0.975) N3(-2.8,-0.975) N4(-2,-0.975) N5(-1.2,-0.975) N8(1.2,-0.975) N9(2,-0.975) N10(2.8,-0.975) N11(3.6,-0.975) N12(4.4,-0.975) P1(-4.4,-1.625) P2(-3.6,-1.625) P3(-2.8,-1.625) P4(-2,-1.625) P5(-1.2,-1.625) P8(1.2,-1.625) P9(2,-1.625) P10(2.8,-1.625) P11(3.6,-1.625) P12(4.4,-1.625) R1(-4.4,-2.275) R2(-3.6,-2.275) R3(-2.8,-2.275) R4(-2,-2.275) R5(-1.2,-2.275) R8(1.2,-2.275) R9(2,-2.275) R10(2.8,-2.275) R11(3.6,-2.275) R12(4.4,-2.275) T1(-4.4,-2.925) T2(-3.6,-2.925) T3(-2.8,-2.925) T4(-2,-2.925) T5(-1.2,-2.925) T8(1.2,-2.925) T9(2,-2.925) T10(2.8,-2.925) T11(3.6,-2.925) T12(4.4,-2.925) U1(-4.4,-3.575) U2(-3.6,-3.575) U3(-2.8,-3.575) U4(-2,-3.575) U5(-1.2,-3.575) U8(1.2,-3.575) U9(2,-3.575) U10(2.8,-3.575) U11(3.6,-3.575) U12(4.4,-3.575) V1(-4.4,-4.225) V2(-3.6,-4.225) V3(-2.8,-4.225) V4(-2,-4.225) V5(-1.2,-4.225) V8(1.2,-4.225) V9(2,-4.225) V10(2.8,-4.225) V11(3.6,-4.225) V12(4.4,-4.225) W1(-4.4,-4.875) W2(-3.6,-4.875) W3(-2.8,-4.875) W4(-2,-4.875) W5(-1.2,-4.875) W8(1.2,-4.875) W9(2,-4.875) W10(2.8,-4.875) W11(3.6,-4.875) W12(4.4,-4.875) Y1(-4.4,-5.525) Y2(-3.6,-5.525) Y3(-2.8,-5.525) Y4(-2,-5.525) Y5(-1.2,-5.525) Y8(1.2,-5.525) Y9(2,-5.525) Y10(2.8,-5.525) Y11(3.6,-5.525) Y12(4.4,-5.525)
  silkscreen extent -5.2,-7.3 5.05,7.45, body extent -5.05,-7.3 5.05,7.3, height 1.06
ICC_TFBGA424_14X14_P050_H1P20_CODE-B0A2 [mm] "MCD_03375"
  round 0.23 smd paste+0.025 mask+0.05: 1A1(-2.75,2.75) 1A3(-1.75,2.75) 1A5(-0.75,2.75) 1A7(0.25,2.75) 1A9(1.25,2.75) 1A11(2.25,2.75) 1B2(-2.25,2.25) 1B4(-1.25,2.25) 1B6(-0.25,2.25) 1B8(0.75,2.25) 1B10(1.75,2.25) 1B12(2.75,2.25) 1C1(-2.75,1.75) 1C3(-1.75,1.75) 1C5(-0.75,1.75) 1C7(0.25,1.75) 1C9(1.25,1.75) 1C11(2.25,1.75) 1D2(-2.25,1.25) 1D4(-1.25,1.25) 1D6(-0.25,1.25) 1D8(0.75,1.25) 1D10(1.75,1.25) 1D12(2.75,1.25) 1E1(-2.75,0.75) 1E3(-1.75,0.75) 1E5(-0.75,0.75) 1E7(0.25,0.75) 1E9(1.25,0.75) 1E11(2.25,0.75) 1F2(-2.25,0.25) 1F4(-1.25,0.25) 1F6(-0.25,0.25) 1F8(0.75,0.25) 1F10(1.75,0.25) 1F12(2.75,0.25) 1G1(-2.75,-0.25) 1G3(-1.75,-0.25) 1G5(-0.75,-0.25) 1G7(0.25,-0.25) 1G9(1.25,-0.25) 1G11(2.25,-0.25) 1H2(-2.25,-0.75) 1H4(-1.25,-0.75) 1H6(-0.25,-0.75) 1H8(0.75,-0.75) 1H10(1.75,-0.75) 1H12(2.75,-0.75) 1J1(-2.75,-1.25) 1J3(-1.75,-1.25) 1J5(-0.75,-1.25) 1J7(0.25,-1.25) 1J9(1.25,-1.25) 1J11(2.25,-1.25) 1K2(-2.25,-1.75) 1K4(-1.25,-1.75) 1K6(-0.25,-1.75) 1K8(0.75,-1.75) 1K10(1.75,-1.75) 1K12(2.75,-1.75) 1L1(-2.75,-2.25) 1L3(-1.75,-2.25) 1L5(-0.75,-2.25) 1L7(0.25,-2.25) 1L9(1.25,-2.25) 1L11(2.25,-2.25) 1M2(-2.25,-2.75) 1M4(-1.25,-2.75) 1M6(-0.25,-2.75) 1M8(0.75,-2.75) 1M10(1.75,-2.75) 1M12(2.75,-2.75) A1(-6.5,6.5) A2(-6,6.5) A3(-5.5,6.5) A6(-4,6.5) A7(-3.5,6.5) A10(-2,6.5) A11(-1.5,6.5) A14(0,6.5) A15(0.5,6.5) A18(2,6.5) A19(2.5,6.5) A22(4,6.5) A23(4.5,6.5) A26(6,6.5) A27(6.5,6.5) AA1(-6.5,-3.5) AA2(-6,-3.5) AA3(-5.5,-3.5) AA5(-4.5,-3.5) AA7(-3.5,-3.5) AA9(-2.5,-3.5) AA11(-1.5,-3.5) AA13(-0.5,-3.5) AA15(0.5,-3.5) AA17(1.5,-3.5) AA19(2.5,-3.5) AA21(3.5,-3.5) AA23(4.5,-3.5) AA25(5.5,-3.5) AA26(6,-3.5) AB1(-6.5,-4) AB2(-6,-4) AB3(-5.5,-4) AB4(-5,-4) AB6(-4,-4) AB8(-3,-4) AB10(-2,-4) AB12(-1,-4) AB14(0,-4) AB16(1,-4) AB18(2,-4) AB20(3,-4) AB22(4,-4) AB24(5,-4) AB25(5.5,-4) AB26(6,-4) AB27(6.5,-4) AC2(-6,-4.5) AC3(-5.5,-4.5) AC5(-4.5,-4.5) AC7(-3.5,-4.5) AC9(-2.5,-4.5) AC11(-1.5,-4.5) AC13(-0.5,-4.5) AC15(0.5,-4.5) AC17(1.5,-4.5) AC19(2.5,-4.5) AC21(3.5,-4.5) AC23(4.5,-4.5) AC25(5.5,-4.5) AC26(6,-4.5) AC27(6.5,-4.5) AD3(-5.5,-5) AD4(-5,-5) AD6(-4,-5) AD8(-3,-5) AD10(-2,-5) AD12(-1,-5) AD14(0,-5) AD16(1,-5) AD18(2,-5) AD20(3,-5) AD22(4,-5) AD24(5,-5) AD25(5.5,-5) AE1(-6.5,-5.5) AE2(-6,-5.5) AE3(-5.5,-5.5) AE4(-5,-5.5) AE5(-4.5,-5.5) AE6(-4,-5.5) AE7(-3.5,-5.5) AE8(-3,-5.5) AE9(-2.5,-5.5) AE10(-2,-5.5) AE11(-1.5,-5.5) AE12(-1,-5.5) AE13(-0.5,-5.5) AE14(0,-5.5) AE15(0.5,-5.5) AE16(1,-5.5) AE17(1.5,-5.5) AE18(2,-5.5) AE19(2.5,-5.5) AE20(3,-5.5) AE21(3.5,-5.5) AE22(4,-5.5) AE23(4.5,-5.5) AE24(5,-5.5) AE25(5.5,-5.5) AE26(6,-5.5) AF1(-6.5,-6) AF2(-6,-6) AF3(-5.5,-6) AF5(-4.5,-6) AF6(-4,-6) AF7(-3.5,-6) AF9(-2.5,-6) AF10(-2,-6) AF11(-1.5,-6) AF13(-0.5,-6) AF14(0,-6) AF15(0.5,-6) AF17(1.5,-6) AF18(2,-6) AF19(2.5,-6) AF21(3.5,-6) AF22(4,-6) AF23(4.5,-6) AF25(5.5,-6) AF26(6,-6) AF27(6.5,-6) AG1(-6.5,-6.5) AG2(-6,-6.5) AG5(-4.5,-6.5) AG6(-4,-6.5) AG9(-2.5,-6.5) AG10(-2,-6.5) AG13(-0.5,-6.5) AG14(0,-6.5) AG17(1.5,-6.5) AG18(2,-6.5) AG21(3.5,-6.5) AG22(4,-6.5) AG25(5.5,-6.5) AG26(6,-6.5) AG27(6.5,-6.5) B1(-6.5,6) B2(-6,6) B3(-5.5,6) B5(-4.5,6) B6(-4,6) B7(-3.5,6) B9(-2.5,6) B10(-2,6) B11(-1.5,6) B13(-0.5,6) B14(0,6) B15(0.5,6) B17(1.5,6) B18(2,6) B19(2.5,6) B21(3.5,6) B22(4,6) B23(4.5,6) B25(5.5,6) B26(6,6) B27(6.5,6) C2(-6,5.5) C3(-5.5,5.5) C4(-5,5.5) C5(-4.5,5.5) C6(-4,5.5) C7(-3.5,5.5) C8(-3,5.5) C9(-2.5,5.5) C10(-2,5.5) C11(-1.5,5.5) C12(-1,5.5) C13(-0.5,5.5) C14(0,5.5) C15(0.5,5.5) C16(1,5.5) C17(1.5,5.5) C18(2,5.5) C19(2.5,5.5) C20(3,5.5) C21(3.5,5.5) C22(4,5.5) C23(4.5,5.5) C24(5,5.5) C25(5.5,5.5) C26(6,5.5) C27(6.5,5.5) D3(-5.5,5) D4(-5,5) D6(-4,5) D8(-3,5) D10(-2,5) D12(-1,5) D14(0,5) D16(1,5) D18(2,5) D20(3,5) D22(4,5) D24(5,5) D25(5.5,5) E1(-6.5,4.5) E2(-6,4.5) E3(-5.5,4.5) E5(-4.5,4.5) E7(-3.5,4.5) E9(-2.5,4.5) E11(-1.5,4.5) E13(-0.5,4.5) E15(0.5,4.5) E17(1.5,4.5) E19(2.5,4.5) E21(3.5,4.5) E23(4.5,4.5) E25(5.5,4.5) E26(6,4.5) F1(-6.5,4) F2(-6,4) F3(-5.5,4) F4(-5,4) F6(-4,4) F8(-3,4) F10(-2,4) F12(-1,4) F14(0,4) F16(1,4) F18(2,4) F20(3,4) F22(4,4) F24(5,4) F25(5.5,4) F26(6,4) F27(6.5,4) G2(-6,3.5) G3(-5.5,3.5) G5(-4.5,3.5) G7(-3.5,3.5) G9(-2.5,3.5) G11(-1.5,3.5) G13(-0.5,3.5) G15(0.5,3.5) G17(1.5,3.5) G19(2.5,3.5) G21(3.5,3.5) G23(4.5,3.5) G25(5.5,3.5) G26(6,3.5) G27(6.5,3.5) H3(-5.5,3) H4(-5,3) H6(-4,3) H22(4,3) H24(5,3) H25(5.5,3) J1(-6.5,2.5) J2(-6,2.5) J3(-5.5,2.5) J5(-4.5,2.5) J7(-3.5,2.5) J21(3.5,2.5) J23(4.5,2.5) J25(5.5,2.5) J26(6,2.5) K1(-6.5,2) K2(-6,2) K3(-5.5,2) K4(-5,2) K6(-4,2) K22(4,2) K24(5,2) K25(5.5,2) K26(6,2) K27(6.5,2) L2(-6,1.5) L3(-5.5,1.5) L5(-4.5,1.5) L7(-3.5,1.5) L21(3.5,1.5) L23(4.5,1.5) L25(5.5,1.5) L26(6,1.5) L27(6.5,1.5) M3(-5.5,1) M4(-5,1) M6(-4,1) M22(4,1) M24(5,1) M25(5.5,1) N1(-6.5,0.5) N2(-6,0.5) N3(-5.5,0.5) N5(-4.5,0.5) N7(-3.5,0.5) N21(3.5,0.5) N23(4.5,0.5) N25(5.5,0.5) N26(6,0.5) P1(-6.5,0) P2(-6,0) P3(-5.5,0) P4(-5,0) P6(-4,0) P22(4,0) P24(5,0) P25(5.5,0) P26(6,0) P27(6.5,0) R2(-6,-0.5) R3(-5.5,-0.5) R5(-4.5,-0.5) R7(-3.5,-0.5) R21(3.5,-0.5) R23(4.5,-0.5) R25(5.5,-0.5) R26(6,-0.5) R27(6.5,-0.5) T3(-5.5,-1) T4(-5,-1) T6(-4,-1) T22(4,-1) T24(5,-1) T25(5.5,-1) U1(-6.5,-1.5) U2(-6,-1.5) U3(-5.5,-1.5) U5(-4.5,-1.5) U7(-3.5,-1.5) U21(3.5,-1.5) U23(4.5,-1.5) U25(5.5,-1.5) U26(6,-1.5) V1(-6.5,-2) V2(-6,-2) V3(-5.5,-2) V4(-5,-2) V6(-4,-2) V22(4,-2) V24(5,-2) V25(5.5,-2) V26(6,-2) V27(6.5,-2) W2(-6,-2.5) W3(-5.5,-2.5) W5(-4.5,-2.5) W7(-3.5,-2.5) W21(3.5,-2.5) W23(4.5,-2.5) W25(5.5,-2.5) W26(6,-2.5) W27(6.5,-2.5) Y3(-5.5,-3) Y4(-5,-3) Y6(-4,-3) Y22(4,-3) Y24(5,-3) Y25(5.5,-3)
  silkscreen extent -7.17,-7 7,7.17, body extent -7,-7 7,7, height 1.21
ICC_UFBGA201_176+25_10X10_P065 [mm] "IPC"
  round 0.25 smd mask+0.038: A1(-4.55,4.55) A2(-3.9,4.55) A3(-3.25,4.55) A4(-2.6,4.55) A5(-1.95,4.55) A6(-1.3,4.55) A7(-0.65,4.55) A8(0,4.55) A9(0.65,4.55) A10(1.3,4.55) A11(1.95,4.55) A12(2.6,4.55) A13(3.25,4.55) A14(3.9,4.55) A15(4.55,4.55) B1(-4.55,3.9) B2(-3.9,3.9) B3(-3.25,3.9) B4(-2.6,3.9) B5(-1.95,3.9) B6(-1.3,3.9) B7(-0.65,3.9) B8(0,3.9) B9(0.65,3.9) B10(1.3,3.9) B11(1.95,3.9) B12(2.6,3.9) B13(3.25,3.9) B14(3.9,3.9) B15(4.55,3.9) C1(-4.55,3.25) C2(-3.9,3.25) C3(-3.25,3.25) C4(-2.6,3.25) C5(-1.95,3.25) C6(-1.3,3.25) C7(-0.65,3.25) C8(0,3.25) C9(0.65,3.25) C10(1.3,3.25) C11(1.95,3.25) C12(2.6,3.25) C13(3.25,3.25) C14(3.9,3.25) C15(4.55,3.25) D1(-4.55,2.6) D2(-3.9,2.6) D3(-3.25,2.6) D4(-2.6,2.6) D5(-1.95,2.6) D6(-1.3,2.6) D7(-0.65,2.6) D8(0,2.6) D9(0.65,2.6) D10(1.3,2.6) D11(1.95,2.6) D12(2.6,2.6) D13(3.25,2.6) D14(3.9,2.6) D15(4.55,2.6) E1(-4.55,1.95) E2(-3.9,1.95) E3(-3.25,1.95) E4(-2.6,1.95) E12(2.6,1.95) E13(3.25,1.95) E14(3.9,1.95) E15(4.55,1.95) F1(-4.55,1.3) F2(-3.9,1.3) F3(-3.25,1.3) F4(-2.6,1.3) F6(-1.3,1.3) F7(-0.65,1.3) F8(0,1.3) F9(0.65,1.3) F10(1.3,1.3) F12(2.6,1.3) F13(3.25,1.3) F14(3.9,1.3) F15(4.55,1.3) G1(-4.55,0.65) G2(-3.9,0.65) G3(-3.25,0.65) G4(-2.6,0.65) G6(-1.3,0.65) G7(-0.65,0.65) G8(0,0.65) G9(0.65,0.65) G10(1.3,0.65) G12(2.6,0.65) G13(3.25,0.65) G14(3.9,0.65) G15(4.55,0.65) H1(-4.55,0) H2(-3.9,0) H3(-3.25,0) H4(-2.6,0) H6(-1.3,0) H7(-0.65,0) H8(0,0) H9(0.65,0) H10(1.3,0) H12(2.6,0) H13(3.25,0) H14(3.9,0) H15(4.55,0) J1(-4.55,-0.65) J2(-3.9,-0.65) J3(-3.25,-0.65) J4(-2.6,-0.65) J6(-1.3,-0.65) J7(-0.65,-0.65) J8(0,-0.65) J9(0.65,-0.65) J10(1.3,-0.65) J12(2.6,-0.65) J13(3.25,-0.65) J14(3.9,-0.65) J15(4.55,-0.65) K1(-4.55,-1.3) K2(-3.9,-1.3) K3(-3.25,-1.3) K4(-2.6,-1.3) K6(-1.3,-1.3) K7(-0.65,-1.3) K8(0,-1.3) K9(0.65,-1.3) K10(1.3,-1.3) K12(2.6,-1.3) K13(3.25,-1.3) K14(3.9,-1.3) K15(4.55,-1.3) L1(-4.55,-1.95) L2(-3.9,-1.95) L3(-3.25,-1.95) L4(-2.6,-1.95) L12(2.6,-1.95) L13(3.25,-1.95) L14(3.9,-1.95) L15(4.55,-1.95) M1(-4.55,-2.6) M2(-3.9,-2.6) M3(-3.25,-2.6) M4(-2.6,-2.6) M5(-1.95,-2.6) M6(-1.3,-2.6) M7(-0.65,-2.6) M8(0,-2.6) M9(0.65,-2.6) M10(1.3,-2.6) M11(1.95,-2.6) M12(2.6,-2.6) M13(3.25,-2.6) M14(3.9,-2.6) M15(4.55,-2.6) N1(-4.55,-3.25) N2(-3.9,-3.25) N3(-3.25,-3.25) N4(-2.6,-3.25) N5(-1.95,-3.25) N6(-1.3,-3.25) N7(-0.65,-3.25) N8(0,-3.25) N9(0.65,-3.25) N10(1.3,-3.25) N11(1.95,-3.25) N12(2.6,-3.25) N13(3.25,-3.25) N14(3.9,-3.25) N15(4.55,-3.25) P1(-4.55,-3.9) P2(-3.9,-3.9) P3(-3.25,-3.9) P4(-2.6,-3.9) P5(-1.95,-3.9) P6(-1.3,-3.9) P7(-0.65,-3.9) P8(0,-3.9) P9(0.65,-3.9) P10(1.3,-3.9) P11(1.95,-3.9) P12(2.6,-3.9) P13(3.25,-3.9) P14(3.9,-3.9) P15(4.55,-3.9) R1(-4.55,-4.55) R2(-3.9,-4.55) R3(-3.25,-4.55) R4(-2.6,-4.55) R5(-1.95,-4.55) R6(-1.3,-4.55) R7(-0.65,-4.55) R8(0,-4.55) R9(0.65,-4.55) R10(1.3,-4.55) R11(1.95,-4.55) R12(2.6,-4.55) R13(3.25,-4.55) R14(3.9,-4.55) R15(4.55,-4.55)
  silkscreen extent -5.22,-5.07 5.07,5.23, body extent -5.07,-5.07 5.07,5.07, height 0.61
ICC_UQFN18-EPAD_2X2P80_P040 [mm] "MCD-02300"
  rect 0.48x0.2 smd mask+0.05: 1(-0.94,0.8) 2(-0.94,0.4) 3(-0.94,0) 4(-0.94,-0.4) 5(-0.94,-0.8) 10(0.94,-0.8) 11(0.94,-0.4) 12(0.94,0) 13(0.94,0.4) 14(0.94,0.8)
  rect 0.2x0.48 smd mask+0.05: 6(-0.6,-1.34) 7(-0.2,-1.34) 8(0.2,-1.34) 9(0.6,-1.34) 15(0.6,1.34) 16(0.2,1.34) 17(-0.2,1.34) 18(-0.6,1.34)
  rect 0.95x1.75 smd mask+0.05: 19(0,0)
  silkscreen extent -1.22,-1.45 1.05,1.63, body extent -1.1,-1.5 1.1,1.5, height 0.41
ICC_WFBGA153_13X11P5_P050 [mm] "MCD-04155"
  round 0.23 smd paste+0.025 mask+0.05: A1(-3.25,-3.25) A2(-3.25,-2.75) A3(-3.25,-2.25) A4(-3.25,-1.75) A5(-3.25,-1.25) A6(-3.25,-0.75) A7(-3.25,-0.25) A8(-3.25,0.25) A9(-3.25,0.75) A10(-3.25,1.25) A11(-3.25,1.75) A12(-3.25,2.25) A13(-3.25,2.75) A14(-3.25,3.25) B1(-2.75,-3.25) B2(-2.75,-2.75) B3(-2.75,-2.25) B4(-2.75,-1.75) B5(-2.75,-1.25) B6(-2.75,-0.75) B7(-2.75,-0.25) B8(-2.75,0.25) B9(-2.75,0.75) B10(-2.75,1.25) B11(-2.75,1.75) B12(-2.75,2.25) B13(-2.75,2.75) B14(-2.75,3.25) C1(-2.25,-3.25) C2(-2.25,-2.75) C3(-2.25,-2.25) C4(-2.25,-1.75) C5(-2.25,-1.25) C6(-2.25,-0.75) C7(-2.25,-0.25) C8(-2.25,0.25) C9(-2.25,0.75) C10(-2.25,1.25) C11(-2.25,1.75) C12(-2.25,2.25) C13(-2.25,2.75) C14(-2.25,3.25) D1(-1.75,-3.25) D2(-1.75,-2.75) D3(-1.75,-2.25) D4(-1.75,-1.75) D12(-1.75,2.25) D13(-1.75,2.75) D14(-1.75,3.25) E1(-1.25,-3.25) E2(-1.25,-2.75) E3(-1.25,-2.25) E5(-1.25,-1.25) E6(-1.25,-0.75) E7(-1.25,-0.25) E8(-1.25,0.25) E9(-1.25,0.75) E10(-1.25,1.25) E12(-1.25,2.25) E13(-1.25,2.75) E14(-1.25,3.25) F1(-0.75,-3.25) F2(-0.75,-2.75) F3(-0.75,-2.25) F5(-0.75,-1.25) F10(-0.75,1.25) F12(-0.75,2.25) F13(-0.75,2.75) F14(-0.75,3.25) G1(-0.25,-3.25) G2(-0.25,-2.75) G3(-0.25,-2.25) G5(-0.25,-1.25) G10(-0.25,1.25) G12(-0.25,2.25) G13(-0.25,2.75) G14(-0.25,3.25) H1(0.25,-3.25) H2(0.25,-2.75) H3(0.25,-2.25) H5(0.25,-1.25) H10(0.25,1.25) H12(0.25,2.25) H13(0.25,2.75) H14(0.25,3.25) J1(0.75,-3.25) J2(0.75,-2.75) J3(0.75,-2.25) J5(0.75,-1.25) J10(0.75,1.25) J12(0.75,2.25) J13(0.75,2.75) J14(0.75,3.25) K1(1.25,-3.25) K2(1.25,-2.75) K3(1.25,-2.25) K5(1.25,-1.25) K6(1.25,-0.75) K7(1.25,-0.25) K8(1.25,0.25) K9(1.25,0.75) K10(1.25,1.25) K12(1.25,2.25) K13(1.25,2.75) K14(1.25,3.25) L1(1.75,-3.25) L2(1.75,-2.75) L3(1.75,-2.25) L12(1.75,2.25) L13(1.75,2.75) L14(1.75,3.25) M1(2.25,-3.25) M2(2.25,-2.75) M3(2.25,-2.25) M4(2.25,-1.75) M5(2.25,-1.25) M6(2.25,-0.75) M7(2.25,-0.25) M8(2.25,0.25) M9(2.25,0.75) M10(2.25,1.25) M11(2.25,1.75) M12(2.25,2.25) M13(2.25,2.75) M14(2.25,3.25) N1(2.75,-3.25) N2(2.75,-2.75) N3(2.75,-2.25) N4(2.75,-1.75) N5(2.75,-1.25) N6(2.75,-0.75) N7(2.75,-0.25) N8(2.75,0.25) N9(2.75,0.75) N10(2.75,1.25) N11(2.75,1.75) N12(2.75,2.25) N13(2.75,2.75) N14(2.75,3.25) P1(3.25,-3.25) P2(3.25,-2.75) P3(3.25,-2.25) P4(3.25,-1.75) P5(3.25,-1.25) P6(3.25,-0.75) P7(3.25,-0.25) P8(3.25,0.25) P9(3.25,0.75) P10(3.25,1.25) P11(3.25,1.75) P12(3.25,2.25) P13(3.25,2.75) P14(3.25,3.25)
  silkscreen extent -6.55,-5.8 6.55,5.8, body extent -6.55,-5.8 6.55,5.8, height 0.81
ICC_WLCSP49_3P46X3P46_P050 [mm] "MCD-02315"
  round 0.23 smd paste+0.025 mask+0.05: A1(-1.5,1.5) A2(-1,1.5) A3(-0.5,1.5) A4(0,1.5) A5(0.5,1.5) A6(1,1.5) A7(1.5,1.5) B1(-1.5,1) B2(-1,1) B3(-0.5,1) B4(0,1) B5(0.5,1) B6(1,1) B7(1.5,1) C1(-1.5,0.5) C2(-1,0.5) C3(-0.5,0.5) C4(0,0.5) C5(0.5,0.5) C6(1,0.5) C7(1.5,0.5) D1(-1.5,0) D2(-1,0) D3(-0.5,0) D4(0,0) D5(0.5,0) D6(1,0) D7(1.5,0) E1(-1.5,-0.5) E2(-1,-0.5) E3(-0.5,-0.5) E4(0,-0.5) E5(0.5,-0.5) E6(1,-0.5) E7(1.5,-0.5) F1(-1.5,-1) F2(-1,-1) F3(-0.5,-1) F4(0,-1) F5(0.5,-1) F6(1,-1) F7(1.5,-1) G1(-1.5,-1.5) G2(-1,-1.5) G3(-0.5,-1.5) G4(0,-1.5) G5(0.5,-1.5) G6(1,-1.5) G7(1.5,-1.5)
  silkscreen extent -1.88,-1.75 1.75,1.88, body extent -1.75,-1.75 1.75,1.75, height 0.67
ICC_WSON8-EPAD_2X2_P050 [mm] "MCD-02194"
  rect 0.5x0.3 smd paste+0 mask+0.05: 1(-0.9,0.75) 2(-0.9,0.25) 3(-0.9,-0.25) 4(-0.9,-0.75) 5(0.9,-0.75) 6(0.9,-0.25) 7(0.9,0.25) 8(0.9,0.75)
  rect 0.9x1.6 smd paste+0 mask+0.05: 9(0,0)
  silkscreen extent -0.5,-1 0.5,1, body extent -1,-1 1,1, height 0.81
IND_0402_MURATA_LQW15AN2N4C00X [mm]
  rect 0.65x0.9 smd mask+0.05: 1(-0.475,0) 2(0.475,0)
  body extent -0.55,-0.35 0.55,0.35, height 0.6
IND_0805_MURATA_LQM21 [mm] "MCD-02317"
  rect 0.85x1.55 smd mask+0.05: 1(-0.875,0) 2(0.875,0)
  silkscreen extent -0.33,-0.72 0.33,0.72, body extent -1.1,-0.72 1.1,0.72, height 1.45
IND_2016_MURATA_LQM2MPN2R2NG0 [mm]
  rect 0.8x1.8 smd mask+0.05: 1(-0.8,0) 2(0.8,0)
  silkscreen extent -0.28,-0.87 0.28,0.87, body extent -1.07,-0.87 1.08,0.87, height 1
IND_2520_TOKO_DFE252012P [mm]
  rect 0.8x2 smd mask+0.05: 1(-1,0) 2(1,0)
  silkscreen extent -1.35,-1.12 1.35,1.12, body extent -1.35,-1.1 1.35,1.1, height 2
L0603 [mm]
  rect 0.8x0.95 smd mask+0.05: 1(-0.8,0) 2(0.8,0)
  silkscreen extent -1.33,-0.6 1.33,0.6, body extent -0.87,-0.47 0.87,0.47, height 0.95
L1210_LQH [mm]
  rect 1.7x3.1 smd mask+0.05: 1(-1.1,0) 2(1.1,0)
  silkscreen extent -2.05,-1.65 2.05,1.65, body extent -1.75,-1.35 1.75,1.35, height 2
LED_0603_OSRAM_LB-Q39G-L2OO-35-1_BLUE_1A2K_H0P4 [mm]
  rect 0.8x0.8 smd mask+0.05: 1(-0.75,0) 2(0.75,0)
  silkscreen extent -0.85,-0.53 1.28,0.53, body extent -0.85,-0.45 0.85,0.45, height 0.6
LED_0603_OSRAM_LG-Q396-PS-35_GREEN_1A2K_H0P4 [mm]
  rect 0.8x0.8 smd mask+0.05: 1(-0.75,0) 2(0.75,0)
  silkscreen extent -0.85,-0.53 1.28,0.53, body extent -0.85,-0.45 0.85,0.45, height 0.6
LED_0603_OSRAM_LO-Q976-PS-25_ORANGE_1A2K_H0P8 [mm]
  rect 0.8x0.8 smd mask+0.05: 1(-0.75,0) 2(0.75,0)
  silkscreen extent -0.85,-0.53 1.28,0.53, body extent -0.85,-0.45 0.85,0.45, height 0.8
LED_0603_VISHAY_VLMS1300-GS08_RED_1A2K_H0P8 [mm]
  rect 0.8x0.8 smd mask+0.05: 1(-0.75,0) 2(0.75,0)
  silkscreen extent -0.85,-0.53 1.28,0.53, body extent -0.85,-0.45 0.85,0.45, height 0.8
LED_BI-GR_WE-150141SV73110 [mm] "MCD-02631"
  rect 1.1x1.5 smd mask+0.05: 1(-0.75,1.5) 2(0.75,1.5) 3(-0.75,-1.5) 4(0.75,-1.5)
  silkscreen extent -1.65,-1.85 1.5,1.7, body extent -1.5,-1.85 1.5,1.85, height 2.1
LINK200 [mm]
  rect 0.2x0.35 smd paste-10 mask+0.05: 1(0,-0.225) 2(0,0.225)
